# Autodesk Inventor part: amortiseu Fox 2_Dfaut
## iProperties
Created: 2006-03
Part Number: amortiseu Fox 2_Dfaut
Document SubType Name: Modeling
Designer: Flavien MARTY
Author: Flavien MARTY
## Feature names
1. Base1
